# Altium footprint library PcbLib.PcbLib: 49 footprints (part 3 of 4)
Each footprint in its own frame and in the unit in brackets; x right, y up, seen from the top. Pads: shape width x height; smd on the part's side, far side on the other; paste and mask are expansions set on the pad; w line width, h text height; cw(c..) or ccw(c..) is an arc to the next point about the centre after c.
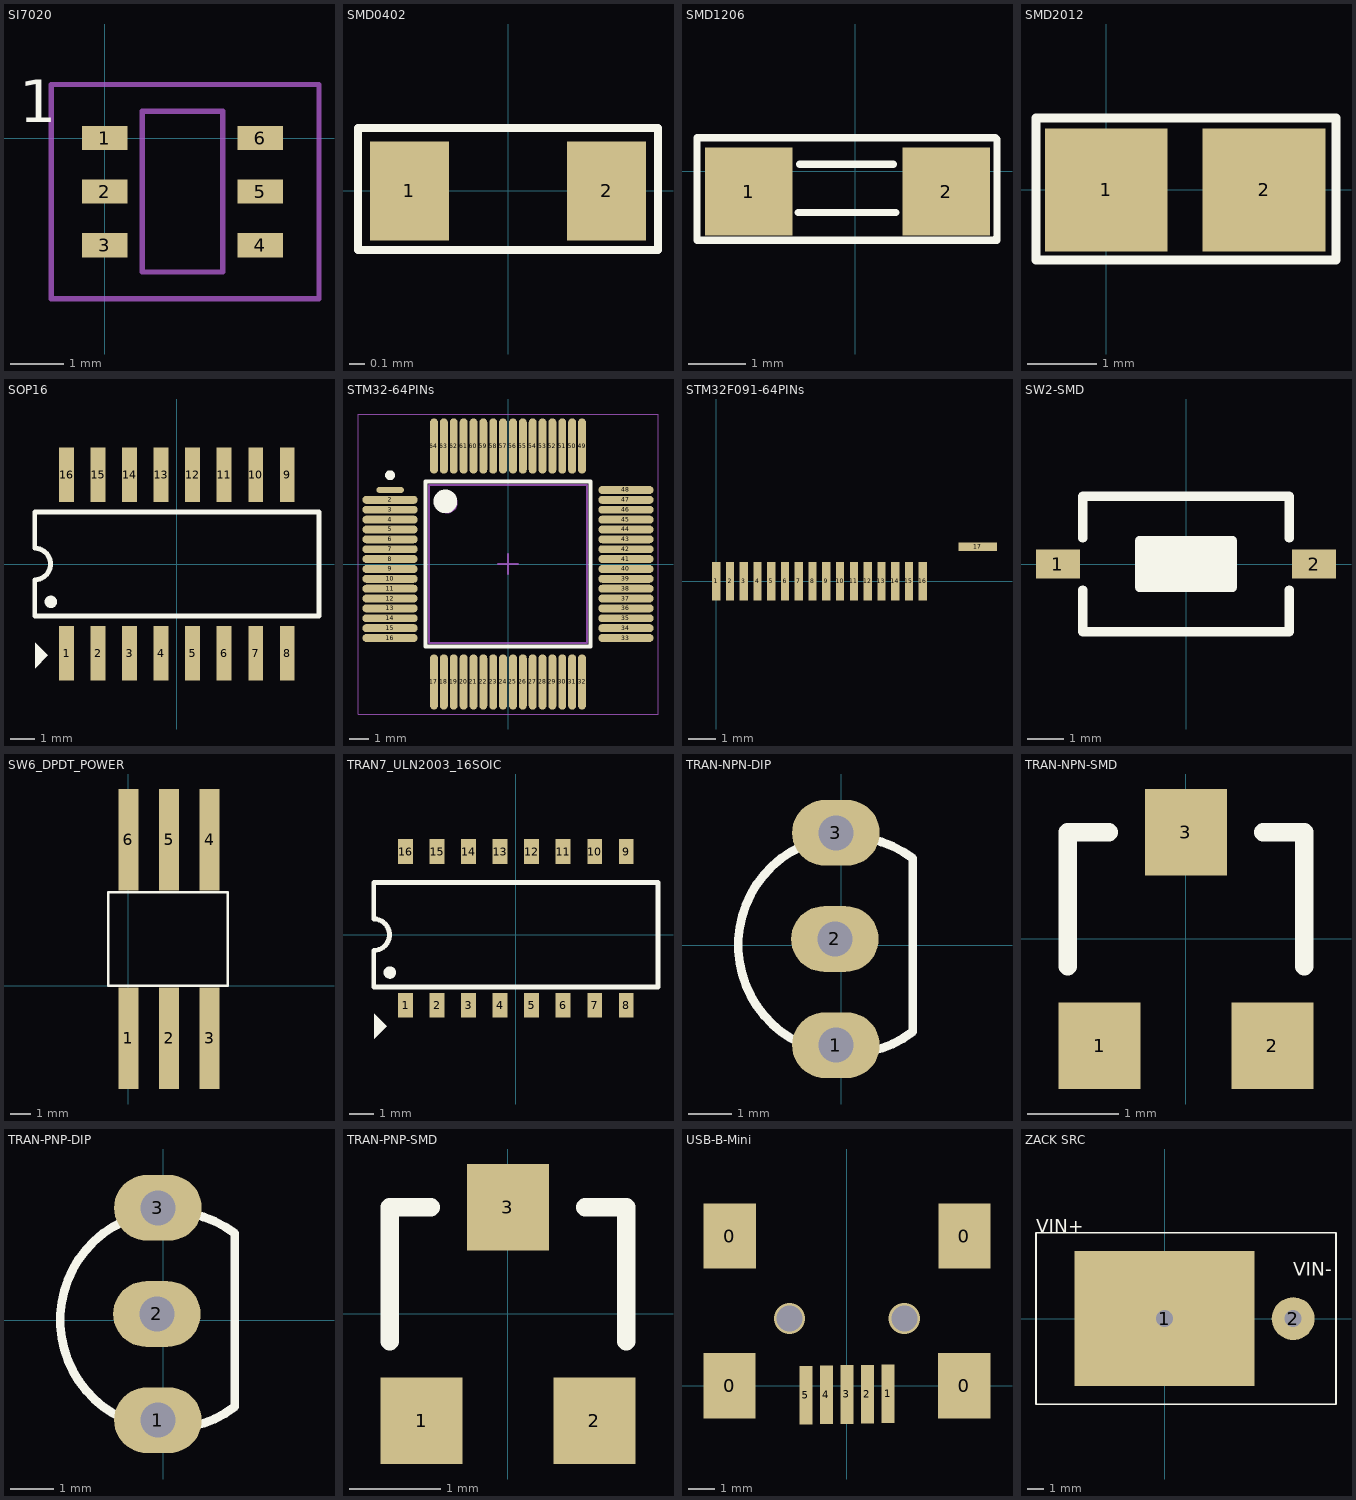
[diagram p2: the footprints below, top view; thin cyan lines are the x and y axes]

## SI7020 [mm] "DFN, 4-Leads, Body 3.00x3.00mm, Pitch 0.65mm, IPC Medium Density"
height 0.8
pads (6):
  rect 0.85x0.45 smd: 1(0,0) 2(0,-1) 3(0,-2) 4(2.9,-2) 5(2.9,-1) 6(2.9,0)
Top Overlay:
  text "1" at -1.6,0.3 h0.8
Mechanical 1:
  lines w0.1: 2.2,-2.3 2.2,-2.5 0.7,-2.5 0.7,0.5 2.2,0.5 ; -1,-3 -1,1 4,1 4,-3 -1,-3
Mechanical 13:
  lines w0.1: 2.2,-2.3 2.2,0.5

## SMD0402 [mil]
pads (2):
  rect 20x25 smd: 1(-25,0) 2(25,0)
Top Overlay:
  lines w2: -38,-15 -38,16 38,16 38,-15 -38,-15
3D body "User Library-Chip Resistor_0402 (1005).STEP": height 14.37, standoff 0, extent -19.68,-9.76 19.68,10

## SMD1206 [mil]
pads (2):
  rect 60x60 smd: 1(-72.68,-13.74) 2(62.32,-13.74)
Top Overlay:
  lines w5: -39,-28 28,-28 ; -38,5 26,5 ; 96,-46 97,-47 ; 96,23 -108,23 -108,-47 97,-47 ; 97,22 97,-47
3D body "SW3DPS-RESISTOR 1206-DEFAULT.STEP": height 20.87, standoff -1.18, extent -68.99,-45.67 57,19.68

## SMD2012 [mil]
pads (2):
  rect 70x70 smd: 1(0,0) 2(90,0)
Top Overlay:
  lines w5: -40,-40 -40,41 131,41 131,-40 -40,-40
3D body "User Library-CAPC2012X___.STEP": height 25, standoff -25, extent 7.64,-11.44 86.37,11

## SOP16 [mm] "Small Outline; 16 Leads; Body Width 5.6 mm; Pitch 1.27 mm"
height 2
pads (16):
  rect 0.6x2.2 smd: 1(-4.445,-3.6) 2(-3.175,-3.6) 3(-1.905,-3.6) 4(-0.635,-3.6) 5(0.635,-3.6) 6(1.905,-3.6) 7(3.175,-3.6) 8(4.445,-3.6) 9(4.445,3.6) 10(3.175,3.6) 11(1.905,3.6) 12(0.635,3.6) 13(-0.635,3.6) 14(-1.905,3.6) 15(-3.175,3.6) 16(-4.445,3.6)
Top Overlay:
  circle w0.25: c-5.078,-1.524 r0.125
  region: -5.715,-4.191 -5.207,-3.683 -5.715,-3.175
  lines w0.2: -5.725,-2.1 -5.725,-0.635 ccw(c-5.725,0) -5.725,0.635 -5.725,2.1 5.725,2.1 5.725,-2.1 -5.725,-2.1

## STM32-64PINs [mm] "SQFP, 64-Leads, Body 8.00x8.00mm, Pitch 0.50mm, IPC Medium Density"
height 2.45
pads (64):
  oval 1.4x0.3 smd: 1(-5.975,3.75)
  oval 2.8x0.4 smd: 2(-5.975,3.25) 3(-5.975,2.75) 4(-5.975,2.25) 5(-5.975,1.75) 6(-5.975,1.25) 7(-5.975,0.75) 8(-5.975,0.25) 9(-5.975,-0.25) 10(-5.975,-0.75) 11(-5.975,-1.25) 12(-5.975,-1.75) 13(-5.975,-2.25) 14(-5.975,-2.75) 15(-5.975,-3.25) 16(-5.975,-3.75) 33(5.975,-3.75) 34(5.975,-3.25) 35(5.975,-2.75) 36(5.975,-2.25) 37(5.975,-1.75) 38(5.975,-1.25) 39(5.975,-0.75) 40(5.975,-0.25) 41(5.975,0.25) 42(5.975,0.75) 43(5.975,1.25) 44(5.975,1.75) 45(5.975,2.25) 46(5.975,2.75) 47(5.975,3.25) 48(5.975,3.75)
  oval 0.4x2.8 smd: 17(-3.75,-5.975) 18(-3.25,-5.975) 19(-2.75,-5.975) 20(-2.25,-5.975) 21(-1.75,-5.975) 22(-1.25,-5.975) 23(-0.75,-5.975) 24(-0.25,-5.975) 25(0.25,-5.975) 26(0.75,-5.975) 27(1.25,-5.975) 28(1.75,-5.975) 29(2.25,-5.975) 30(2.75,-5.975) 31(3.25,-5.975) 32(3.75,-5.975) 49(3.75,5.975) 50(3.25,5.975) 51(2.75,5.975) 52(2.25,5.975) 53(1.75,5.975) 54(1.25,5.975) 55(0.75,5.975) 56(0.25,5.975) 57(-0.25,5.975) 58(-0.75,5.975) 59(-1.25,5.975) 60(-1.75,5.975) 61(-2.25,5.975) 62(-2.75,5.975) 63(-3.25,5.975) 64(-3.75,5.975)
Top Overlay:
  circle w0.6: c-3.175,3.175 r0.3
  circle w0.25: c-5.975,4.5 r0.125
  lines w0.2: -4.175,-4.175 4.175,-4.175 4.175,4.175 -4.175,4.175 -4.175,-4.175
Mechanical 13:
  circle w0.1: c-3.1,3.1 r0.5
  lines w0.1: -4,-4 4,-4 4,4 -4,4 -4,-4
Mechanical 15:
  lines w0.05: -7.6,-7.6 7.6,-7.6 7.6,7.6 -7.6,7.6 -7.6,-7.6
  lines w0.1: -0.5,0 0.5,0 ; 0,-0.5 0,0.5
3D body: height 2.45, standoff 0.25, extent -4,-4 4,4

## STM32F091-64PINs [mm]
pads (17):
  rect 0.3x1.4 smd: 1(0,0) 2(0.5,0) 3(1,0) 4(1.5,0) 5(2,0) 6(2.5,0) 7(3,0) 8(3.5,0) 9(4,0) 10(4.5,0) 11(5,0) 12(5.5,0) 13(6,0) 14(6.5,0) 15(7,0) 16(7.5,0)
  rect 1.4x0.3 smd: 17(9.5,1.25)

## SW2-SMD [mm] "Switch SMD type"
pads (2):
  rect 1.2x0.8 smd: 1(-3.5,0) 2(3.5,0)
Top Overlay:
  rectangle: -1.27,-0.635 1.27,0.635
  lines w0.254: -2.819,-0.711 -2.819,-1.854 2.819,-1.854 2.819,-0.711 ; -2.819,0.711 -2.819,1.854 2.819,1.854 2.819,0.711 ; -1.27,-0.635 -1.27,0.635 1.27,0.635 1.27,-0.635 -1.27,-0.635
3D body "User Library-Button-SMD.step": height 2.5, standoff 0, extent -3.05,-1.85 3.05,1.85

## SW6_DPDT_POWER [mm] "PUSH POWER SOURCE"
pads (6):
  rect 1x5 smd: 1(0,-2.6) 2(2,-2.6) 3(4,-2.6) 4(4,7.2) 5(2,7.2) 6(0,7.2)
Top Overlay:
  lines w0.13: 4.9,4.6 4.9,0 -1,0 -1,4.6 4.9,4.6 ; 4.9,4.6 4.9,4.6
3D body "User Library-PVB6_EE.step": height 12.5, standoff -1, extent -3.05,-3.85 6.85,8.65

## TRAN7_ULN2003_16SOIC [mm] "Small Outline; 16 Leads; Body Width 5.6 mm; Pitch 1.27 mm"
height 2
pads (16):
  rect 0.6x1 smd: 1(-4.445,-2.838) 2(-3.175,-2.838) 3(-1.905,-2.838) 4(-0.635,-2.838) 5(0.635,-2.838) 6(1.905,-2.838) 7(3.175,-2.838) 8(4.445,-2.838) 9(4.445,3.346) 10(3.175,3.346) 11(1.905,3.346) 12(0.635,3.346) 13(-0.635,3.346) 14(-1.905,3.346) 15(-3.175,3.346) 16(-4.445,3.346)
Top Overlay:
  circle w0.25: c-5.078,-1.524 r0.125
  region: -5.715,-4.191 -5.207,-3.683 -5.715,-3.175
  lines w0.2: -5.725,-2.1 -5.725,-0.635 ccw(c-5.725,0) -5.725,0.635 -5.725,2.1 5.725,2.1 5.725,-2.1 -5.725,-2.1
3D body "User Library-SOIC-16-1.step": height 1.4, standoff 0, extent -4.95,-2.746 4.95,3.254

## TRAN-NPN-DIP [mm] "TO, Flat Index; 3 In-Line, Axial Leads; Body Dia. 4.5mm; Leads 0.51 x 0.48 mm (max)"
height 6.86
pads (3):
  oval 2x1.5 hole 0.8: 1(-0.127,-2.286) 2(-0.151,0.139) 3(-0.127,2.564)
Top Overlay:
  lines w0.2: 1.627,-1.98 cw(c0.127,0) 1.627,1.98 1.627,-1.98
3D body "BJT.step": height 11, standoff -1, extent -2.476,-2.794 1.524,3.006

## TRAN-NPN-SMD [mm] "SOT-23; 3 Leads; Body 3.0 x 2.5 mm, inc. leads (LxW max)"
height 1.2
pads (3):
  rect 0.9x0.95 smd: 1(-0.95,-1.175) 2(0.95,-1.175) 3(0,1.175)
Top Overlay:
  lines w0.2: -1.3,-0.3 -1.3,1.175 -0.85,1.175 ; 0.85,1.175 1.3,1.175 1.3,-0.3
3D body "CircuitWorks-SOT-23.step": height 1.06, standoff -0.04, extent -1.5,-1.439 1.5,1.061

## TRAN-PNP-DIP [mm] "TO, Flat Index; 3 In-Line, Axial Leads; Body Dia. 4.5mm; Leads 0.51 x 0.48 mm (max)"
height 6.86
pads (3):
  oval 2x1.5 hole 0.8: 1(-0.127,-2.286) 2(-0.151,0.139) 3(-0.127,2.564)
Top Overlay:
  lines w0.2: 1.627,-1.98 cw(c0.127,0) 1.627,1.98 1.627,-1.98
3D body "BJT.step": height 11, standoff -1, extent -2.476,-2.794 1.524,3.006

## TRAN-PNP-SMD [mm] "SOT-23; 3 Leads; Body 3.0 x 2.5 mm, inc. leads (LxW max)"
height 1.2
pads (3):
  rect 0.9x0.95 smd: 1(-0.95,-1.175) 2(0.95,-1.175) 3(0,1.175)
Top Overlay:
  lines w0.2: -1.3,-0.3 -1.3,1.175 -0.85,1.175 ; 0.85,1.175 1.3,1.175 1.3,-0.3
3D body "CircuitWorks-SOT-23.step": height 1.06, standoff -0.04, extent -1.5,-1.377 1.5,1.123

## USB-B-Mini [mm]
pads (9):
  rect 2x2.5 smd: 0(-4.5,0) 0(-4.496,5.74) 0(4.5,0) 0(4.504,5.74)
  rect 0.5x2.25 smd: 1(1.575,-0.305) 2(0.787,-0.318) 3(0,-0.33) 4(-0.787,-0.343) 5(-1.575,-0.356)
via 2.2,2.58 diameter 1.2 hole 1
via -2.2,2.58 diameter 1.2 hole 1
3D body "User Library-USB_mini_B.step": height 3.95, standoff -1, extent -5.35,-0.673 5.35,8.527

## ZACK SRC [mm] "HEADER, SINGLE, DISTANCE = 100mil"
pads (2):
  rect 10.668x8.001 hole 1: 1(0,0)
  round 2.54 hole 1: 2(7.62,0)
Top Overlay:
  lines w0.1: -7.62,-5.08 10.16,-5.08 10.16,5.08 -7.62,5.08 -7.62,-5.08
  lines w0.254: -1.778,-1.905 -1.778,1.778 5.08,1.778 5.08,-1.905 -1.778,-1.905
  text "VIN-" at 7.62,2.54 h0.8
  text "VIN+" at -7.62,5.08 h0.8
